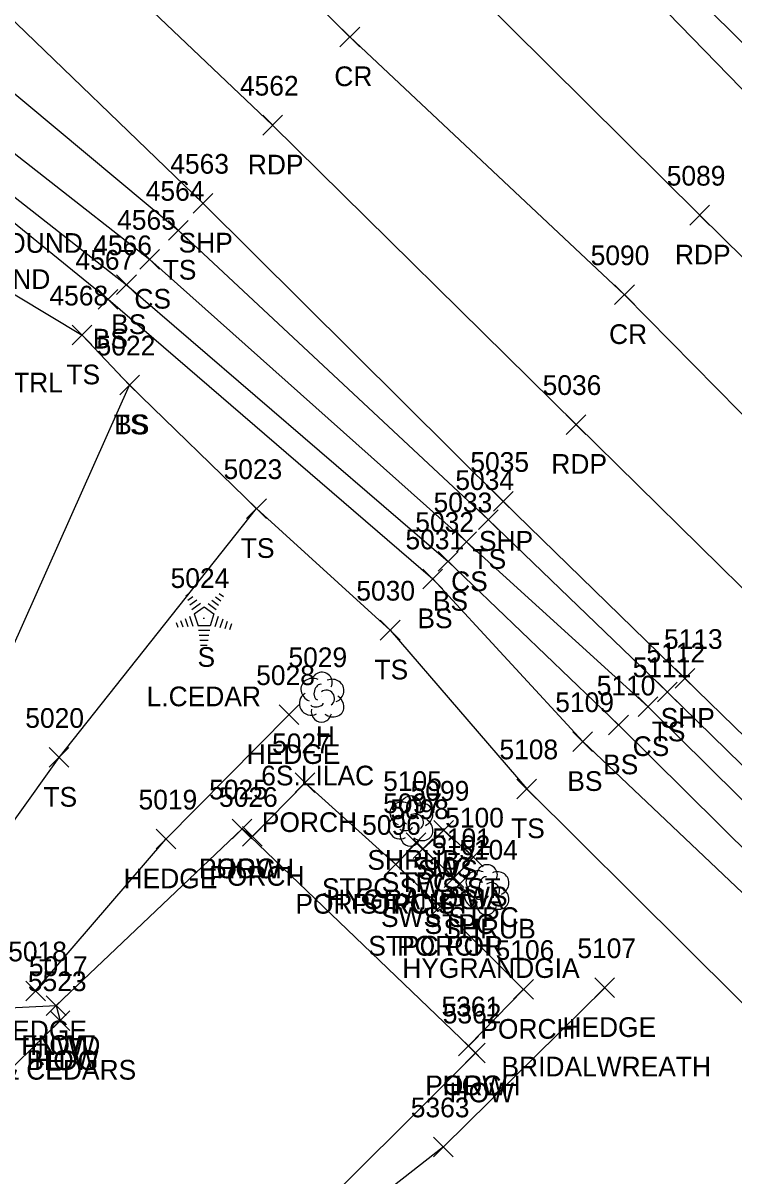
# Model space of a CAD drawing. Extents: x 1472233 to 1475777, y 540726 to 543442.
# Drawn here: x 1474664.3 to 1474736.3, y 541480.4 to 541597.4 of the extents above; entities that cross this region are included whole.
import ezdxf

# ---------------------------------------------------------------- set-up
doc = ezdxf.new("R2010")
doc.units = 0
for name, color, linetype in [('C_A', 7, 'Continuous'), ('L_A', 7, 'Continuous'), ('L_C', 7, 'Continuous'), ('L_I', 7, 'Continuous'), ('L_TIC', 7, 'Continuous'), ('LAHR', 7, 'Continuous'), ('LBC', 7, 'Continuous'), ('LBF', 7, 'Continuous'), ('LELB', 7, 'Continuous'), ('LFNC', 7, 'Continuous'), ('LSH', 7, 'Continuous'), ('LTC', 7, 'Continuous'), ('LTD', 7, 'Continuous'), ('M_C', 7, 'Continuous'), ('P_A', 7, 'Continuous'), ('P_I', 7, 'Continuous'), ('P_TIC', 7, 'Continuous'), ('PET', 7, 'Continuous'), ('PRC', 7, 'Continuous'), ('PSP', 7, 'Continuous'), ('R_A', 7, 'Continuous'), ('R_I', 7, 'Continuous'), ('R_TIC', 7, 'Continuous'), ('RSW', 7, 'Continuous')]:
    doc.layers.add(name, color=color, linetype=linetype)

msp = doc.modelspace()

# ---------------------------------------------------------------- linework, layer by layer
at = {"layer": 'L_TIC'}
for points in [[(1474679, 541575.33), (1474681, 541577.33)], [(1474681, 541575.33), (1474679, 541577.33)], [(1474676.09, 541572.39), (1474678.09, 541574.39)], [(1474678.09, 541572.39), (1474676.09, 541574.39)], [(1474673.74, 541569.81), (1474675.74, 541571.81)], [(1474675.74, 541569.81), (1474673.74, 541571.81)], [(1474671.87, 541568.34), (1474673.87, 541570.34)], [(1474673.87, 541568.34), (1474671.87, 541570.34)], [(1474669.24, 541564.71), (1474671.24, 541566.71)], [(1474671.24, 541564.71), (1474669.24, 541566.71)], [(1474674.05, 541559.64), (1474676.05, 541561.64)], [(1474676.05, 541559.64), (1474674.05, 541561.64)], [(1474674.05, 541559.64), (1474676.05, 541561.64)], [(1474676.05, 541559.64), (1474674.05, 541561.64)], [(1474686.92, 541547.1), (1474688.92, 541549.1)], [(1474688.92, 541547.1), (1474686.92, 541549.1)], [(1474686.92, 541547.1), (1474688.92, 541549.1)], [(1474688.92, 541547.1), (1474686.92, 541549.1)], [(1474710.41, 541545.99), (1474712.41, 541547.99)], [(1474712.41, 541545.99), (1474710.41, 541547.99)], [(1474708.21, 541543.73), (1474710.21, 541545.73)], [(1474710.21, 541543.73), (1474708.21, 541545.73)], [(1474706.35, 541541.74), (1474708.35, 541543.74)], [(1474708.35, 541541.74), (1474706.35, 541543.74)], [(1474704.79, 541539.97), (1474706.79, 541541.97)], [(1474706.79, 541539.97), (1474704.79, 541541.97)], [(1474700.47, 541534.77), (1474702.47, 541536.77)], [(1474702.47, 541534.77), (1474700.47, 541536.77)], [(1474728.58, 541528.49), (1474730.58, 541530.49)], [(1474730.58, 541528.49), (1474728.58, 541530.49)], [(1474690.22, 541526.2), (1474692.22, 541528.2)], [(1474692.22, 541526.2), (1474690.22, 541528.2)], [(1474726.62, 541527), (1474728.62, 541529)], [(1474728.62, 541527), (1474726.62, 541529)], [(1474723.62, 541525.15), (1474725.62, 541527.15)], [(1474725.62, 541525.15), (1474723.62, 541527.15)], [(1474719.99, 541523.46), (1474721.99, 541525.46)], [(1474721.99, 541523.46), (1474719.99, 541525.46)], [(1474666.91, 541521.86), (1474668.91, 541523.86)], [(1474668.91, 541521.86), (1474666.91, 541523.86)], [(1474691.84, 541519.29), (1474693.84, 541521.29)], [(1474693.84, 541519.29), (1474691.84, 541521.29)], [(1474714.32, 541518.67), (1474716.32, 541520.67)], [(1474716.32, 541518.67), (1474714.32, 541520.67)], [(1474685.46, 541514.6), (1474687.46, 541516.6)], [(1474687.46, 541514.6), (1474685.46, 541516.6)], [(1474685.46, 541514.6), (1474687.46, 541516.6)], [(1474687.46, 541514.6), (1474685.46, 541516.6)], [(1474677.74, 541513.58), (1474679.74, 541515.58)], [(1474679.74, 541513.58), (1474677.74, 541515.58)], [(1474686.51, 541513.84), (1474688.51, 541515.84)], [(1474688.51, 541513.84), (1474686.51, 541515.84)], [(1474703.1, 541513.21), (1474705.1, 541515.21)], [(1474705.1, 541513.21), (1474703.1, 541515.21)], [(1474703.81, 541512.6), (1474705.81, 541514.6)], [(1474705.81, 541512.6), (1474703.81, 541514.6)], [(1474701.03, 541511.01), (1474703.03, 541513.01)], [(1474703.03, 541511.01), (1474701.03, 541513.01)], [(1474701.03, 541511.01), (1474703.03, 541513.01)], [(1474703.03, 541511.01), (1474701.03, 541513.01)], [(1474706.93, 541509.66), (1474708.93, 541511.66)], [(1474708.93, 541509.66), (1474706.93, 541511.66)], [(1474707.44, 541508.95), (1474709.44, 541510.95)], [(1474709.44, 541508.95), (1474707.44, 541510.95)], [(1474705.55, 541506.75), (1474707.55, 541508.75)], [(1474707.55, 541506.75), (1474705.55, 541508.75)], [(1474705.55, 541506.75), (1474707.55, 541508.75)], [(1474707.55, 541506.75), (1474705.55, 541508.75)], [(1474664.52, 541498.17), (1474666.52, 541500.17)], [(1474666.52, 541498.17), (1474664.52, 541500.17)], [(1474713.99, 541498.32), (1474715.99, 541500.32)], [(1474715.99, 541498.32), (1474713.99, 541500.32)], [(1474722.23, 541498.5), (1474724.23, 541500.5)], [(1474724.23, 541498.5), (1474722.23, 541500.5)], [(1474666.61, 541496.68), (1474668.61, 541498.68)], [(1474668.61, 541496.68), (1474666.61, 541498.68)], [(1474666.61, 541496.68), (1474668.61, 541498.68)], [(1474668.61, 541496.68), (1474666.61, 541498.68)], [(1474666.61, 541496.68), (1474668.61, 541498.68)], [(1474668.61, 541496.68), (1474666.61, 541498.68)], [(1474667, 541495.15), (1474669, 541497.15)], [(1474669, 541495.15), (1474667, 541497.15)], [(1474667, 541495.15), (1474669, 541497.15)], [(1474669, 541495.15), (1474667, 541497.15)], [(1474708.41, 541492.59), (1474710.41, 541494.59)], [(1474710.41, 541492.59), (1474708.41, 541494.59)], [(1474708.41, 541492.59), (1474710.41, 541494.59)], [(1474710.41, 541492.59), (1474708.41, 541494.59)], [(1474709.11, 541491.87), (1474711.11, 541493.87)], [(1474711.11, 541491.87), (1474709.11, 541493.87)], [(1474705.87, 541482.35), (1474707.87, 541484.35)], [(1474707.87, 541482.35), (1474705.87, 541484.35)]]:
    msp.add_lwpolyline(points, dxfattribs=at)
at = {"layer": 'LAHR'}
for points in [[(1474665.52, 541499.17), (1474678.74, 541514.58), (1474691.22, 541527.2)], [(1474723.23, 541499.5), (1474706.87, 541483.35), (1474693.53, 541472.9), (1474703.2, 541466.16), (1474706.3, 541458), (1474706.12, 541446.61)]]:
    msp.add_lwpolyline(points, dxfattribs=at)
at = {"layer": 'LBC'}
for points in [[(1474667.61, 541497.68), (1474686.46, 541515.6), (1474709.41, 541493.59), (1474710.11, 541492.87), (1474691.12, 541473.88), (1474690.31, 541474.24)], [(1474667.61, 541497.68), (1474668, 541496.15)], [(1474690.31, 541474.24), (1474681.97, 541466.12), (1474679, 541463.39), (1474632.94, 541418.86), (1474609.18, 541443.15), (1474603.1, 541449.36), (1474629.16, 541474.87), (1474637.46, 541466.3), (1474668, 541496.15)]]:
    msp.add_lwpolyline(points, dxfattribs=at)
at = {"layer": 'LBF'}
for points in [[(1474686.46, 541515.6), (1474687.51, 541514.84), (1474692.84, 541520.29), (1474702.03, 541512.01), (1474706.55, 541507.75), (1474714.99, 541499.32), (1474709.41, 541493.59)], [(1474702.03, 541512.01), (1474704.1, 541514.21), (1474704.81, 541513.6), (1474707.93, 541510.66), (1474708.44, 541509.95), (1474706.55, 541507.75)]]:
    msp.add_lwpolyline(points, dxfattribs=at)
at = {"layer": 'LELB'}
for points in [[(1474874.35, 541686.34), (1474843.02, 541683.96), (1474803.71, 541674.06), (1474781.9, 541670.96), (1474757.18, 541659.71), (1474724.18, 541638.54), (1474717.86, 541626.89), (1474722.01, 541623.04), (1474720.87, 541620.26), (1474718.25, 541617.83), (1474721.79, 541611.05), (1474727.93, 541604.53), (1474740.37, 541592.25), (1474769.12, 541563.74), (1474804.5, 541530.53), (1474827.9, 541507.87), (1474842.4, 541494.13), (1474851.95, 541493.37)], [(1474658.26, 541594.47), (1474680, 541576.33), (1474711.41, 541546.99), (1474729.58, 541529.49), (1474758.17, 541501.53)], [(1474655.52, 541590.28), (1474677.09, 541573.39), (1474709.21, 541544.73), (1474727.62, 541528), (1474761.24, 541494.71)], [(1474651.86, 541586.42), (1474653.08, 541587.79), (1474674.74, 541570.81), (1474707.35, 541542.74), (1474724.62, 541526.15), (1474758.93, 541492.18), (1474757.24, 541490.11)], [(1474648.94, 541585.29), (1474649.71, 541583.91), (1474651.86, 541586.42), (1474672.87, 541569.34), (1474705.79, 541540.97), (1474720.99, 541524.46), (1474757.24, 541490.11)], [(1474649.71, 541583.91), (1474650.51, 541577.57), (1474670.24, 541565.71), (1474675.05, 541560.64), (1474687.92, 541548.1), (1474701.47, 541535.77), (1474715.32, 541519.67), (1474747.44, 541487.74), (1474755.53, 541485.45), (1474760.16, 541487.57), (1474764.63, 541494.68), (1474758.17, 541501.53)], [(1474604.13, 541515.41), (1474629.66, 541503.42), (1474648.03, 541511.45), (1474660.67, 541528.45), (1474675.05, 541560.64)], [(1474626.74, 541495.38), (1474654.68, 541504.32), (1474667.91, 541522.86), (1474687.92, 541548.1)]]:
    msp.add_lwpolyline(points, dxfattribs=at)
at = {"layer": 'LFNC'}
msp.add_lwpolyline([(1474580.23, 541467.4), (1474576.45, 541470.44), (1474585.11, 541484.14), (1474607.46, 541509.89), (1474626.74, 541495.38), (1474655.27, 541497.07), (1474667.61, 541497.68)], dxfattribs=at)
at = {"layer": 'LSH'}
for p, q in [((1474703.53, 541516.46), (1474703.53, 541516.46)), ((1474703.53, 541516.46), (1474703.53, 541516.46)), ((1474711.24, 541509.49), (1474711.24, 541509.49)), ((1474711.24, 541509.49), (1474711.24, 541509.49))]:
    msp.add_line(p, q, dxfattribs=at)
for centre in [(1474703.58, 541517.9), (1474711.29, 541510.93)]:
    msp.add_arc(centre, 1.05, 335.5272, 180.9563, dxfattribs=at)
for centre, major_axis, ratio, start_param, end_param in [((1474702.74, 541517.13), (1.21, -0.51), 0.895232, 1.570796, 4.712389), ((1474703.33, 541516.92), (-0.208, -0.792), 0.645439, 3.141593, 6.283185), ((1474704.58, 541517.05), (-1.14, -0.48), 0.949671, 1.570796, 4.712389), ((1474702.45, 541515.76), (0.58, -1.04), 0.959034, 3.141593, 6.283185), ((1474704.03, 541516.3), (-0.5, 0.667), 0.989748, 3.141593, 6.283185), ((1474704.53, 541515.63), (-1.09, 0.79), 0.841452, 1.570796, 4.712389), ((1474703.53, 541514.96), (0.26, 1.06), 0.942809, 1.570796, 4.712389), ((1474703.08, 541515.71), (-0.625, -0.083), 0.423636, 0, 3.141593), ((1474710.45, 541510.16), (1.21, -0.51), 0.895232, 1.570796, 4.712389), ((1474711.04, 541509.95), (-0.208, -0.792), 0.645439, 3.141593, 6.283185), ((1474712.29, 541510.08), (-1.14, -0.48), 0.949671, 1.570796, 4.712389), ((1474710.16, 541508.78), (0.58, -1.04), 0.959034, 3.141593, 6.283185), ((1474711.74, 541509.33), (-0.5, 0.667), 0.989748, 3.141593, 6.283185), ((1474712.24, 541508.66), (-1.09, 0.79), 0.841452, 1.570796, 4.712389), ((1474711.24, 541507.99), (0.26, 1.06), 0.942809, 1.570796, 4.712389), ((1474710.79, 541508.74), (-0.625, -0.083), 0.423636, 0, 3.141593)]:
    msp.add_ellipse(centre, major_axis=major_axis, ratio=ratio, start_param=start_param, end_param=end_param, dxfattribs=at)
at = {"layer": 'LTC'}
for p, q in [((1474680.75, 541539.26), (1474681.1, 541539.52)), ((1474680.95, 541538.8), (1474681.48, 541539.18)), ((1474681.16, 541538.33), (1474681.87, 541538.84)), ((1474683.4, 541538.81), (1474684.08, 541538.31)), ((1474683.77, 541539.15), (1474684.32, 541538.76)), ((1474684.14, 541539.5), (1474684.56, 541539.2)), ((1474681.37, 541537.87), (1474682.25, 541538.5)), ((1474681.6, 541537.41), (1474682.61, 541538.14)), ((1474682.61, 541538.14), (1474683.61, 541537.42)), ((1474683.03, 541538.46), (1474683.84, 541537.87)), ((1474683.61, 541537.42), (1474683.22, 541536.22)), ((1474679.78, 541536.54), (1474679.93, 541536.07)), ((1474680.23, 541536.76), (1474680.44, 541536.11)), ((1474680.69, 541536.97), (1474680.96, 541536.14)), ((1474681.14, 541537.19), (1474681.47, 541536.17)), ((1474681.6, 541537.41), (1474681.99, 541536.22)), ((1474684.04, 541537.15), (1474683.71, 541536.11)), ((1474684.49, 541536.9), (1474684.2, 541536.01)), ((1474684.93, 541536.65), (1474684.7, 541535.92)), ((1474685.38, 541536.4), (1474685.19, 541535.82)), ((1474683.22, 541536.22), (1474681.99, 541536.22)), ((1474683.18, 541535.72), (1474682.03, 541535.72)), ((1474683.09, 541535.22), (1474682.11, 541535.22)), ((1474683.01, 541534.72), (1474682.18, 541534.72)), ((1474682.93, 541534.22), (1474682.25, 541534.22))]:
    msp.add_line(p, q, dxfattribs=at)
at = {"layer": 'LTD'}
msp.add_line((1474694.5, 541529.02), (1474694.5, 541529.02), dxfattribs=at)
msp.add_line((1474694.5, 541529.02), (1474694.5, 541529.02), dxfattribs=at)
msp.add_arc((1474694.55, 541530.45), 1.05, 335.5272, 180.9563, dxfattribs=at)
for centre, major_axis, ratio, start_param, end_param in [((1474693.71, 541529.68), (1.21, -0.51), 0.895232, 1.570796, 4.712389), ((1474695.55, 541529.6), (-1.14, -0.48), 0.949671, 1.570796, 4.712389), ((1474693.42, 541528.31), (0.58, -1.04), 0.959034, 3.141593, 6.283185), ((1474694.3, 541529.48), (-0.208, -0.792), 0.645439, 3.141593, 6.283185), ((1474695, 541528.85), (-0.5, 0.667), 0.989748, 3.141593, 6.283185), ((1474694.05, 541528.27), (-0.625, -0.083), 0.423636, 0, 3.141593), ((1474695.5, 541528.18), (-1.09, 0.79), 0.841452, 1.570796, 4.712389), ((1474694.51, 541527.52), (0.26, 1.06), 0.942809, 1.570796, 4.712389)]:
    msp.add_ellipse(centre, major_axis=major_axis, ratio=ratio, start_param=start_param, end_param=end_param, dxfattribs=at)
at = {"layer": 'P_TIC'}
for points in [[(1474696.38, 541594.96), (1474698.38, 541596.96)], [(1474698.38, 541594.96), (1474696.38, 541596.96)], [(1474688.55, 541586), (1474690.55, 541588)], [(1474690.55, 541586), (1474688.55, 541588)], [(1474681.49, 541578.08), (1474683.49, 541580.08)], [(1474683.49, 541578.08), (1474681.49, 541580.08)], [(1474731.85, 541576.87), (1474733.85, 541578.87)], [(1474733.85, 541576.87), (1474731.85, 541578.87)], [(1474724.23, 541568.8), (1474726.23, 541570.8)], [(1474726.23, 541568.8), (1474724.23, 541570.8)], [(1474719.32, 541555.63), (1474721.32, 541557.63)], [(1474721.32, 541555.63), (1474719.32, 541557.63)], [(1474711.93, 541547.83), (1474713.93, 541549.83)], [(1474713.93, 541547.83), (1474711.93, 541549.83)], [(1474730.36, 541529.87), (1474732.36, 541531.87)], [(1474732.36, 541529.87), (1474730.36, 541531.87)]]:
    msp.add_lwpolyline(points, dxfattribs=at)
at = {"layer": 'PET'}
for points in [[(1474257.17, 542041.35), (1474290.36, 542008.95), (1474318.16, 541982.22), (1474353.09, 541947.73), (1474380.11, 541921.32), (1474409.43, 541892.59), (1474448.11, 541855.39), (1474480.03, 541823.99), (1474515.94, 541789.15), (1474551.47, 541754.04), (1474586.76, 541720.19), (1474622.34, 541685.28), (1474642.2, 541667.03), (1474678.81, 541632.27), (1474705.96, 541604.58), (1474732.85, 541577.87), (1474757.56, 541553.54), (1474794.98, 541517.97), (1474838.32, 541475.71), (1474843.05, 541471.26), (1474873.72, 541441.3), (1474901.31, 541414.4), (1474940.73, 541376.24), (1474987.96, 541330.09)], [(1474271.84, 541992.5), (1474300.43, 541965.08), (1474335.42, 541930.7), (1474362.69, 541903.91), (1474391.74, 541875.76), (1474430.66, 541838.97), (1474463.16, 541806.71), (1474497.44, 541771.82), (1474534.45, 541737.95), (1474570.53, 541702.62), (1474603.93, 541669.8), (1474626.86, 541647.27), (1474658.6, 541616.43), (1474689.55, 541587), (1474720.32, 541556.63), (1474739.09, 541538.17), (1474777.3, 541501.31), (1474812.28, 541467.45), (1474846.29, 541433.48), (1474886.23, 541395.48), (1474928.35, 541354.56)]]:
    msp.add_lwpolyline(points, dxfattribs=at)
at = {"layer": 'PRC'}
msp.add_lwpolyline([(1474281.21, 542000.69), (1474310.2, 541973.13), (1474344.4, 541939.36), (1474371.7, 541912.83), (1474400.48, 541884.47), (1474439.86, 541846.82), (1474471.42, 541815.51), (1474506.94, 541781.08), (1474542.71, 541746.15), (1474579.05, 541711.03), (1474614.12, 541676.77), (1474633.39, 541657.93), (1474670.29, 541622.53), (1474697.38, 541595.96), (1474725.23, 541569.8), (1474748.55, 541546.13), (1474786.39, 541510.34), (1474828.43, 541468.79), (1474834.71, 541462.78), (1474865.12, 541432.62), (1474893.04, 541405.96), (1474931.99, 541367.84), (1474980.87, 541320.53)], dxfattribs=at)
at = {"layer": 'PSP'}
for points in [[(1474265.44, 542049.86), (1474298.91, 542017.38), (1474326.56, 541991.3), (1474361.97, 541956.51), (1474389.69, 541929.81), (1474418.37, 541901.23), (1474456.83, 541864.16), (1474490.58, 541830.55), (1474524.38, 541798.05), (1474560.68, 541763.05), (1474595.63, 541729.03), (1474633.71, 541692.09), (1474657.27, 541669.76), (1474686.76, 541641.13), (1474717.31, 541611.08), (1474740.7, 541587.01), (1474766.39, 541561.38), (1474803.05, 541525.86), (1474836.41, 541493.68)], [(1474265.14, 541984.76), (1474291.83, 541959.1), (1474328.22, 541923.56), (1474355.74, 541897.07), (1474384.44, 541868.92), (1474422.85, 541831.66), (1474454.58, 541800.99), (1474488.7, 541768.03), (1474526.59, 541730.75), (1474563.47, 541694.73), (1474596.29, 541662.37), (1474619.45, 541640.43), (1474638.96, 541621.2), (1474660.7, 541600.09), (1474682.49, 541579.08), (1474712.93, 541548.83), (1474731.36, 541530.87), (1474769.83, 541493.4), (1474794.06, 541469.93), (1474805.88, 541458.43), (1474839.61, 541425.83), (1474879.04, 541388.28), (1474920.91, 541347.07)]]:
    msp.add_lwpolyline(points, dxfattribs=at)
at = {"layer": 'R_TIC'}
for points in [[(1474705.9, 541514.47), (1474707.9, 541516.47)], [(1474707.9, 541514.47), (1474705.9, 541516.47)], [(1474703.81, 541512.6), (1474705.81, 541514.6)], [(1474705.81, 541512.6), (1474703.81, 541514.6)], [(1474708.91, 541511.75), (1474710.91, 541513.75)], [(1474710.91, 541511.75), (1474708.91, 541513.75)], [(1474706.93, 541509.66), (1474708.93, 541511.66)], [(1474708.93, 541509.66), (1474706.93, 541511.66)]]:
    msp.add_lwpolyline(points, dxfattribs=at)
at = {"layer": 'RSW'}
msp.add_lwpolyline([(1474704.81, 541513.6), (1474706.9, 541515.47), (1474709.91, 541512.75), (1474707.93, 541510.66)], dxfattribs=at)

# ---------------------------------------------------------------- texts
at = {"layer": 'C_A'}
msp.add_text('HVCTRL', height=2, dxfattribs=at).set_placement((1474657.59, 541559.89))
at = {"layer": 'L_A'}
for s, p in [('TS', (1474678.41, 541571.33)), ('CS', (1474675.54, 541568.39)), ('BS', (1474673.18, 541565.81)), ('BS', (1474671.32, 541564.34)), ('TS', (1474668.65, 541560.71)), ('TS', (1474673.46, 541555.64)), ('BS', (1474673.49, 541555.64)), ('TS', (1474686.33, 541543.1)), ('TS', (1474686.33, 541543.1)), ('TS', (1474709.82, 541541.99)), ('CS', (1474707.65, 541539.73)), ('BS', (1474705.8, 541537.74)), ('BS', (1474704.23, 541535.97)), ('S', (1474681.94, 541532.05)), ('TS', (1474699.88, 541530.77)), ('H', (1474693.94, 541524.02)), ('TS', (1474727.99, 541524.49)), ('CS', (1474726.06, 541523)), ('HEDGE', (1474686.92, 541522.2)), ('BS', (1474723.06, 541521.15)), ('BS', (1474719.43, 541519.46)), ('TS', (1474666.32, 541517.86)), ('PORCH', (1474688.46, 541515.29)), ('TS', (1474713.73, 541514.67)), ('SHRUB', (1474699.16, 541511.46)), ('PORCH', (1474682.08, 541510.6)), ('PORCH', (1474683.13, 541509.84)), ('HOW', (1474683.85, 541510.6)), ('HEDGE', (1474674.44, 541509.58)), ('STPC SWS ST', (1474694.55, 541508.6)), ('STPC', (1474700.61, 541509.21)), ('POR STPC ST', (1474691.86, 541507.01)), ('PORCH', (1474697.65, 541507.01)), ('SWS STPC', (1474700.54, 541505.66)), ('STPC', (1474704.96, 541504.95)), ('SHRUB', (1474706.87, 541504.49)), ('STPC POR', (1474699.25, 541502.75)), ('PORCH', (1474702.17, 541502.75)), ('HEDGE', (1474718.93, 541494.5)), ('HEDGE', (1474661.22, 541494.17)), ('PORCH', (1474710.61, 541494.32)), ('FNWD', (1474664.07, 541492.68)), ('HOW', (1474664.99, 541492.68)), ('HOW', (1474664.99, 541492.68)), ('BLDG', (1474664.59, 541491.15)), ('HOW', (1474665.38, 541491.15)), ('PORCH', (1474705.03, 541488.59)), ('HOW', (1474706.79, 541488.59)), ('HOW', (1474707.49, 541487.87))]:
    msp.add_text(s, height=2, dxfattribs=at).set_placement(p)
at = {"layer": 'L_C'}
for s, p in [('L.CEDAR', (1474676.78, 541528.05)), ('6S.LILAC', (1474688.4, 541520.02)), ('HYGRANDGIA', (1474694.99, 541507.46)), ('HYGRANDGIA', (1474702.7, 541500.49)), ('LILACS & CEDARS', (1474652.09, 541490.17)), ('BRIDALWREATH', (1474712.75, 541490.5))]:
    msp.add_text(s, height=2, dxfattribs=at).set_placement(p)
at = {"layer": 'L_I'}
for s, p in [('4564', (1474676.69, 541579.33)), ('4565', (1474673.79, 541576.39)), ('4566', (1474671.37, 541573.81)), ('4567', (1474669.57, 541572.34)), ('4568', (1474666.93, 541568.71)), ('5022', (1474671.71, 541563.64)), ('5022', (1474671.71, 541563.64)), ('5023', (1474684.58, 541551.1)), ('5023', (1474684.58, 541551.1)), ('5034', (1474708.08, 541549.99)), ('5033', (1474705.87, 541547.73)), ('5032', (1474704.02, 541545.74)), ('5031', (1474703.02, 541543.97)), ('5024', (1474679.21, 541540.05)), ('5030', (1474698.04, 541538.77)), ('5029', (1474691.16, 541532.02)), ('5112', (1474727.45, 541532.49)), ('5111', (1474726.06, 541531)), ('5028', (1474687.89, 541530.2)), ('5110', (1474722.41, 541529.15)), ('5109', (1474718.21, 541527.46)), ('5020', (1474664.48, 541525.86)), ('5027', (1474689.5, 541523.29)), ('5108', (1474712.55, 541522.67)), ('5105', (1474700.76, 541519.46)), ('5025', (1474683.12, 541518.6)), ('5025', (1474683.12, 541518.6)), ('5026', (1474684.12, 541517.84)), ('5019', (1474675.96, 541517.58)), ('5097', (1474700.76, 541517.21)), ('5098', (1474701.47, 541516.6)), ('5096', (1474698.63, 541515.01)), ('5096', (1474698.63, 541515.01)), ('5101', (1474705.73, 541513.66)), ('5102', (1474705.67, 541512.95)), ('5104', (1474708.47, 541512.49)), ('5103', (1474703.77, 541510.75)), ('5103', (1474703.77, 541510.75)), ('5018', (1474662.75, 541502.17)), ('5106', (1474712.16, 541502.32)), ('5107', (1474720.45, 541502.5)), ('5017', (1474664.84, 541500.68)), ('5017', (1474664.84, 541500.68)), ('5017', (1474664.84, 541500.68)), ('5523', (1474664.74, 541499.15)), ('5523', (1474664.74, 541499.15)), ('5361', (1474706.67, 541496.59)), ('5361', (1474706.67, 541496.59)), ('5362', (1474706.8, 541495.87)), ('5363', (1474703.56, 541486.35))]:
    msp.add_text(s, height=2, dxfattribs=at).set_placement(p)
at = {"layer": 'LTC'}
msp.add_text('.', height=1.04, rotation=270, dxfattribs=at).set_placement((1474682.49, 541537.16))
at = {"layer": 'M_C'}
for s, p in [('4"X4" VTHD CONC 3" ABOVE GROUND', (1474621.25, 541574.05)), ('4"X4" VTHD CONC 6" ABOVE GROUND', (1474617.95, 541570.38))]:
    msp.add_text(s, height=2, dxfattribs=at).set_placement(p)
at = {"layer": 'P_A'}
for s, p in [('CR', (1474695.81, 541590.96)), ('RDP', (1474687.04, 541582)), ('SHP', (1474680.02, 541574.08)), ('RDP', (1474730.34, 541572.87)), ('CR', (1474723.66, 541564.8)), ('RDP', (1474717.81, 541551.63)), ('SHP', (1474710.47, 541543.83)), ('SHP', (1474728.89, 541525.87))]:
    msp.add_text(s, height=2, dxfattribs=at).set_placement(p)
at = {"layer": 'P_I'}
for s, p in [('4562', (1474686.24, 541590)), ('4563', (1474679.18, 541582.08)), ('5089', (1474729.51, 541580.87)), ('5090', (1474721.8, 541572.8)), ('5036', (1474716.93, 541559.63)), ('5035', (1474709.6, 541551.83)), ('5113', (1474729.23, 541533.87))]:
    msp.add_text(s, height=2, dxfattribs=at).set_placement(p)
at = {"layer": 'R_A'}
for s, p in [('SWS', (1474704.27, 541510.47)), ('STPC SWS ST', (1474694.55, 541508.6)), ('SWS', (1474707.28, 541507.75)), ('SWS STPC', (1474700.54, 541505.66))]:
    msp.add_text(s, height=2, dxfattribs=at).set_placement(p)
at = {"layer": 'R_I'}
for s, p in [('5099', (1474703.55, 541518.47)), ('5098', (1474701.47, 541516.6)), ('5100', (1474707.05, 541515.75)), ('5101', (1474705.73, 541513.66))]:
    msp.add_text(s, height=2, dxfattribs=at).set_placement(p)

doc.saveas('drawing.dxf')
